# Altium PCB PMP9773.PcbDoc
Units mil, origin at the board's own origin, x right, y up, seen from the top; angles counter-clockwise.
Board outline 1500 x 600 mil, 2 copper layers (Top Layer, Bottom Layer), stack 62 mil thick; 36 components, 24 nets, 102 pads, 186 vias.
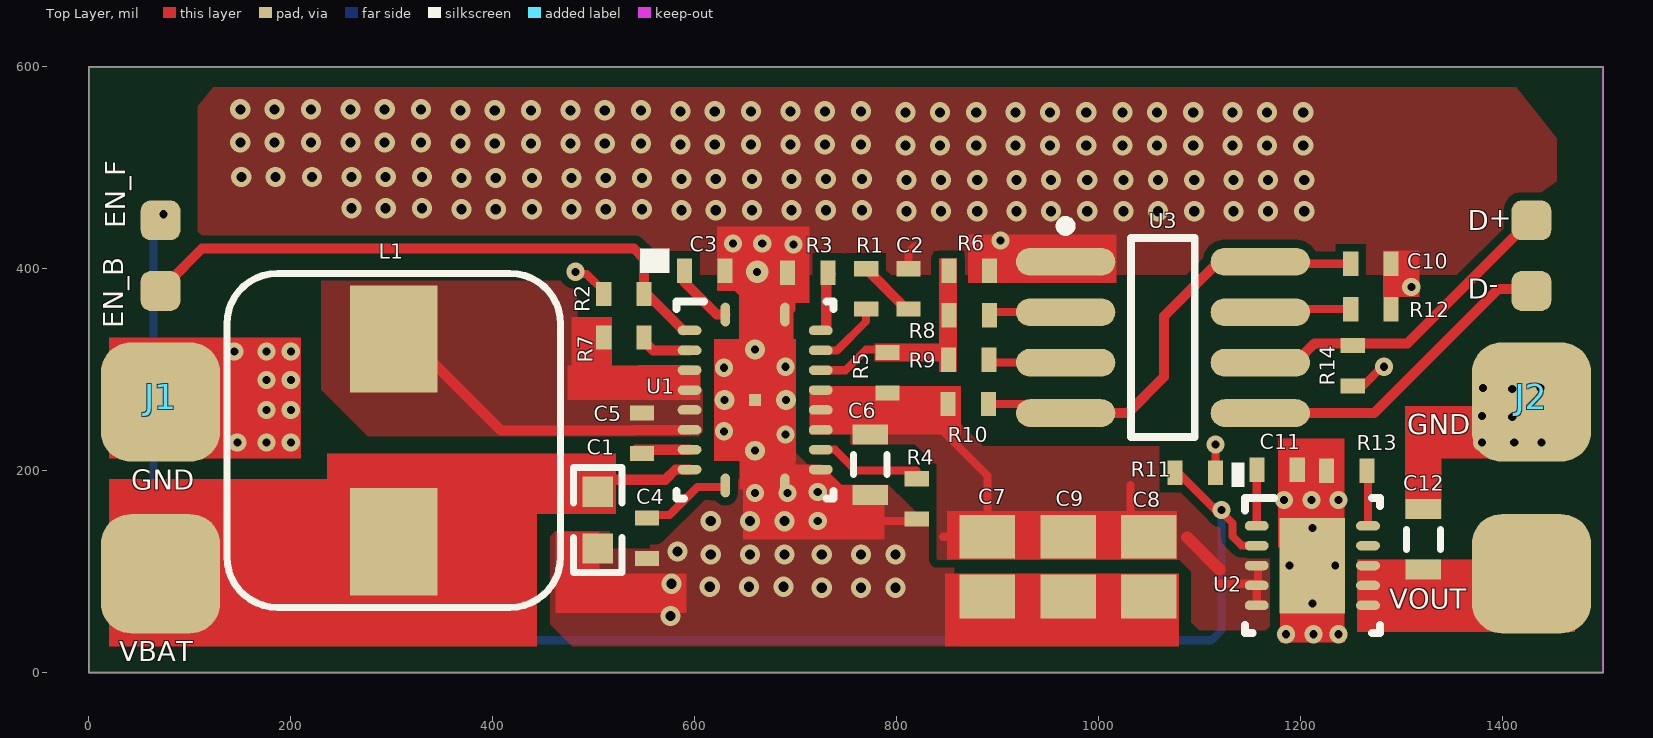
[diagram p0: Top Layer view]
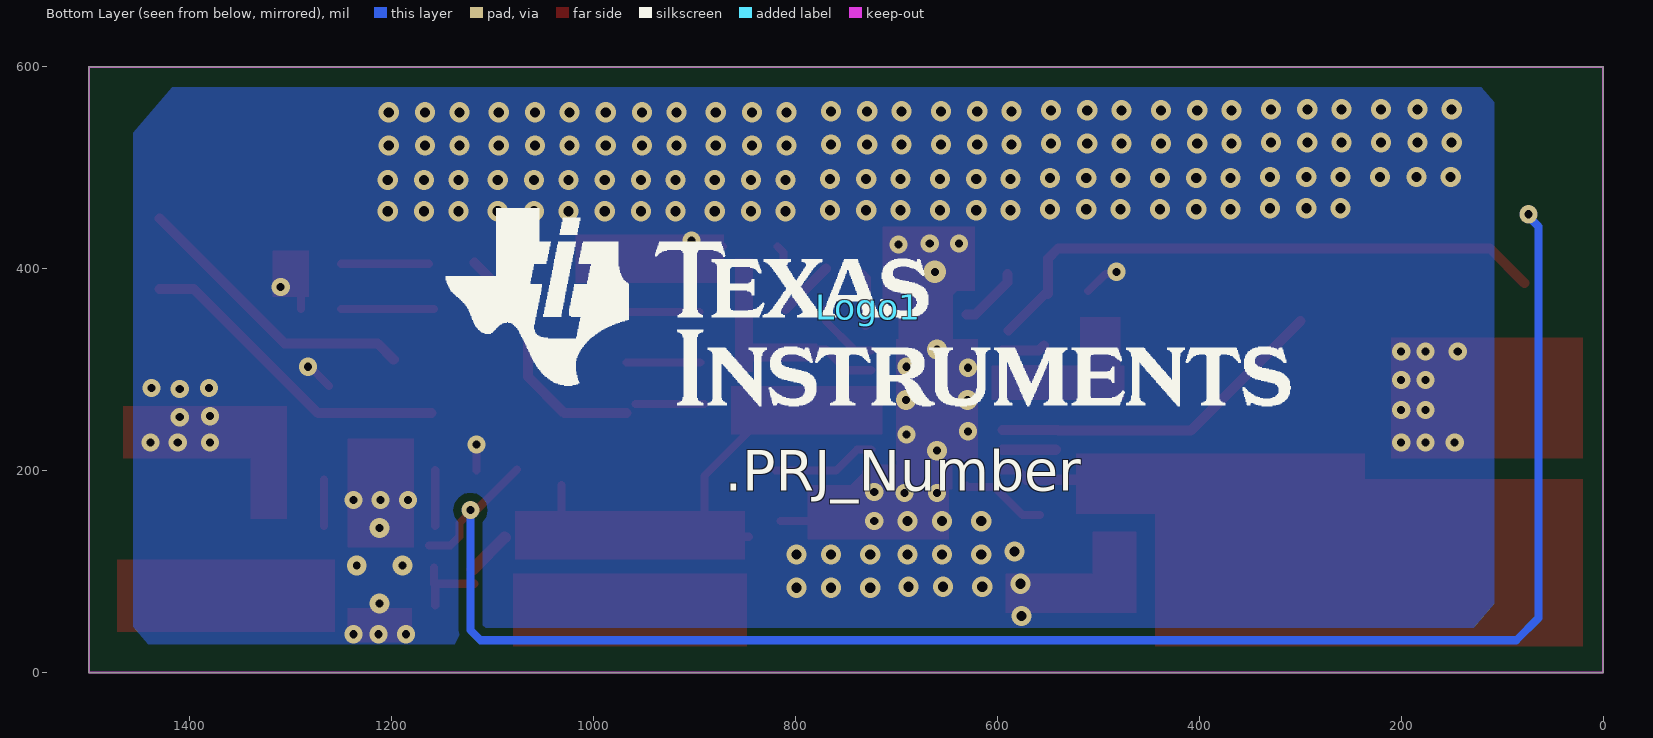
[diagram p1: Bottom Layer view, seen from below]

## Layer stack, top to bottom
Top Layer: signal copper 1.4
Dielectric: core 59.2, FR-4, Dk 4.8
Bottom Layer: signal copper 1.4

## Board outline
0,0 0,600 1500,600 1500,0

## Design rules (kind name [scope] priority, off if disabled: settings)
AcuteAngle [All] p1: minimum=4.50000000000000E+0001 checktracksonly=FALSE
AssemblyTestPointUsage [All] p1: valid=2
Clearance "Small Clearance" [InComponent('U1')] p1: gap=8
Clearance Clearance_BoardEdge_MountingHoles [OnCopper and InComponentClass('Mounting Holes') vs IsKeepOut] p2: gap=8
Clearance Clearance_BoardEdge_Poly [OnCopper and InPoly vs IsKeepOut] p3: gap=10
Clearance Clearance_BoardEdge [OnCopper and Not InComponentClass('Logo') and not InComponentClass('FiducialMark') and not InRegion(1000,500,4000,800) vs IsKeepOut] p4: gap=10
Clearance [All] p5: gap=8
ComponentClearance ComponentClearance_SHUNT [InComponentClass('Shunt')] p1: gap=0 collisioncheckmode=3 verticalgap=0 showdistances=FALSE
ComponentClearance ComponentClearance_Logo [All] p2: gap=10 collisioncheckmode=3 verticalgap=10 showdistances=FALSE
ComponentClearance ComponentClearance_ScrewToNut [(HasFootprint('NY PMS 440 0025 PH')) vs (HasFootprint('Keystone_1902C'))] p3: gap=5 collisioncheckmode=3 verticalgap=10 showdistances=FALSE
ComponentClearance ComponentClearance_MountingHoles [InComponentClass('Mounting Holes')] p4: gap=250 collisioncheckmode=3 verticalgap=100000 showdistances=FALSE
ComponentClearance ComponentClearance_SmallPassives [HasFootprint('0201*') or HasFootprint('0402*') or HasFootprint('0508') or HasFootprint('0603*') or HasFootprint('0612') or HasFootprint('0805*') or HasFootprint('0815*') or HasFootprint('0830*') or HasFootprint('1206*') or HasFootprint('1210*') or HasFootprint('1808*') or HasFootprint('1812*') or HasFootprint('1825*') or HasFootprint('2010*') or HasFootprint('2220*') or HasFootprint('2225*') or HasFootprint('2512*') or HasFootprint('2728*') or HasFootprint('3518*') vs HasFootprint('0201*') or HasFootprint('0402*') or HasFootprint('0508') or HasFootprint('0603*') or HasFootprint('0612') or HasFootprint('0805*') or HasFootprint('0815*') or HasFootprint('0830*') or HasFootprint('1206*') or HasFootprint('1210*') or HasFootprint('1808*') or HasFootprint('1812*') or HasFootprint('1825*') or HasFootprint('2010*') or HasFootprint('2220*') or HasFootprint('2225*') or HasFootprint('2512*') or HasFootprint('2728*') or HasFootprint('3518*')] p5: gap=20 collisioncheckmode=3 verticalgap=10 showdistances=FALSE
ComponentClearance ComponentClearance_THtoSMT [IsThruComponent vs IsSMTComponent] p6 off: gap=10 collisioncheckmode=3 verticalgap=100000 showdistances=FALSE
ComponentClearance ComponentClearance_THtoTH [IsThruComponent vs IsThruComponent] p7: gap=10.11 collisioncheckmode=3 verticalgap=100000 showdistances=FALSE
ComponentClearance [All] p8: gap=16 collisioncheckmode=3 verticalgap=10 showdistances=FALSE
DiffPairsRouting [All] p1: maxlimit=100 minlimit=10 mostfreqgap=10 maxuncoupledlength=1000
FabricationTestPointUsage TestPointUsage [All] p1: valid=2 allowmultiple=FALSE
FabricationTestpoint Testpoint [All] p1: side=3 testpointundercomponent=TRUE minsize=40 maxsize=100 preferedsize=60 minholesize=0 maxholesize=40 preferedholesize=32 testpointgrid=1 allowsidetop=TRUE allowsidebottom=TRUE usegrid=TRUE gridtolerance=0.01
FanoutControl Fanout_LCC [IsLCC] p1: bgadir=Out bgaviamode=Centered fanoutstyle=Auto fanoutdirection=Alternating viagrid=1 // Fanout_LCC (Default Rule)
FanoutControl Fanout_BGA [IsBGA] p2: bgadir=Out bgaviamode=Centered fanoutstyle=Auto fanoutdirection=Alternating viagrid=1 // Fanout_BGA (Default Rule)
FanoutControl Fanout_Default [All] p4: bgadir=Out bgaviamode=Centered fanoutstyle=Auto fanoutdirection=Alternating viagrid=1 // Fanout_Default (Default Rule)
FanoutControl Fanout_Small [(CompPinCount < 5)] p5: bgadir=Out bgaviamode=Centered fanoutstyle=Auto fanoutdirection=OutThenIn viagrid=1 // Fanout_Small (Default Rule)
HoleSize [All] p1: absolutevalues=TRUE maxlimit=80 minlimit=3.94 maxpercent=80.000 minpercent=20.000
HoleToHoleClearance [All] p1: gap=5 allowstackedmicrovias=TRUE
MinimumAnnularRing MinimumAnnularRing_small [TouchesRoom('BGA_Room')] p1: minimumring=2.8
MinimumAnnularRing [All] p2: minimumring=5
MinimumSolderMaskSliver MinimumSolderMaskSliver_Logo [InComponentClass('Logo') vs InComponentClass('Logo')] p1: minsoldermaskwidth=0.7
MinimumSolderMaskSliver [All] p2: minsoldermaskwidth=4
PlaneClearance [All] p1: clearance=10
PlaneConnect [All] p1: planeconnectstyle=Direct reliefexpansion=10 reliefentries=4 reliefconductorwidth=10 reliefairgap=10
PolygonConnect PolygonConnect-TH-Relief [IsPoly vs (IsThruPin)  And Not (InComponent('U3'))  And Not (InComponent('U4'))] p1: connectstyle=Direct reliefconductorwidth=20 reliefentries=4 polygonreliefangle="90 Angle" airgapwidth=10
PolygonConnect PolygonConnect-DirectConn [All] p2: connectstyle=Direct reliefconductorwidth=10 reliefentries=4 polygonreliefangle="90 Angle" airgapwidth=10
RoutingVias [All] p1: holewidth=10 width=22 viastyle="Through Hole" minholewidth=5.9 minwidth=11.8 maxholewidth=50 maxwidth=100
SMDToCorner [All] p1: distance=0
SilkToSilkClearance [All] p1: silktosilkclearance=3
SilkscreenOverComponentPads [All] p1: minsilkscreentomaskgap=2
SolderMaskExpansion [All] p1: expansion=1
Width [All] p1: maxlimit=100 minlimit=6 preferedwidth=10 checkconnectedcopper=TRUE
12 further rules are at their usual default settings.

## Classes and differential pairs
component class Logo: Logo1
component class PMP9773_Hardware: Logo1 ZZ1 ZZ2 ZZ3
component class AssemblyNote: ZZ1 ZZ2 ZZ3
component class PMP9773_Main: C1 C2 C3 C4 C5 C6 C7 C8 C9 C10 C11 C12 J1 J2 L1 R1 R2 R3 R4 R5 R6 R7 R8 R9 R10 R11 R12 R13 R14 U1 U2 U3

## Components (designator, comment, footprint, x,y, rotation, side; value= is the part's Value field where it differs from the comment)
C1 "GRM188R61A226ME15D" 0603_100_HV 504,151 r270 top
C2 "GRM155R71H103KA88D" 0402S 812,380 r90 top
C3 "GRM155R71C104KA88D" 0402S 610,398 r0 top
C4 "GRM155R61A473KA01D" 0402S 553,133 r270 top
C5 "GRM155R61C104KA88D" 0402S 548,237 r90 top
C6 "GRM188R61E105KA12D" 0603S 774,206 r270 top
C7 "GRM21BR61E226ME44" 0805L 890,105 r270 top
C8 "GRM21BR61E226ME44" 0805L 1050,105 r270 top
C9 "GRM21BR61E226ME44" 0805L 970,105 r270 top
C10 "GRM155R61A224KE19D" 0402S 1270,405 r0 top
C11 "GRM1535C1H101JDD5D" 0402S 1177,201 r0 top
C12 "GRM188R61E105KA12D" 0603S 1322,132 r90 top
J1 "Connector" Connector 71,198 r180 top
J2 "Connector" Connector 1429,198 r180 top
L1 "744311150" WE-HC4 302,230 r90 top
Logo1 "Texas Instruments" TI_Stacked_Overlay_Small 728,362 r180 bottom
R1 "CRCW04024K70JNED" 0402S 770,380 r270 top
R2 "CRCW04021M00FKED" 0402S 529.99,375 r0 top
R3 "CRCW0402100KFKED" 0402S 712,396 r0 top
R4 "RC0402JR-070RL" 0402s 820,172 r270 top
R5 "CRCW0402316KFKED" 0402S 791,297 r270 top
R6 "CRCW0402100KFKED" 0402S 872,398 r180 top
R7 "CRCW0402332KFKED" 0402S 530,332 r180 top
R8 "CRCW040295K3FKED" 0402S 872,354 r180 top
R9 "CRCW0402127KFKED" 0402S 871.5,309.87 r180 top
R10 "CRCW04023K01FKED" 0402S 871,266 r180 top
R11 "CRCW04021M00FKED" 0402S 1096,198 r180 top
R12 "CRCW0402127KFKED" 0402S 1270,360 r180 top
R13 "CRCW0402100KFKED" 0402S 1246,200 r0 top
R14 "CRCW0402390KJNED" 0402S 1252,304 r90 top
U1 "TPS61088RHLR" RHL0020A 660,270 r0 top
U2 "TPS2592AADRC" DRC0010J 1212,106 r0 top
U3 "CHY100" CHY100 1064,332 r0 top
ZZ1 "These assemblies are ESD sensitive, ESD precautions shall be observed." AssemblyNote 202,1133.11 r0 top
ZZ2 "These assemblies must be clean and free from flux and all contaminants. Use of no clean flux is not acceptable." AssemblyNote 202,1044.56 r0 top
ZZ3 "These assemblies must comply with workmanship standards IPC-A-610 Class 2, unless otherwise specified." AssemblyNote 202,956 r0 top

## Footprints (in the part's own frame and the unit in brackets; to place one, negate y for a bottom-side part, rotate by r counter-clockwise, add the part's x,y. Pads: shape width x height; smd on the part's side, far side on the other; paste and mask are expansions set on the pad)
0402S [mil] "Based on C0402S footprint from PADS legacy"
  rect 15x24 smd: 1(-20,0) 2(20,0)
  body extent -22,-12 22,12, height 24
0402s [mil] "Based on C0402S footprint from PADS legacy"
  rect 15x24 smd: 1(-20,0) 2(20,0)
  body extent -22,-12 22,12, height 24
0603_100_HV [mil] "SMD, 2-Leads, Body 1.6x0.8mm"
  rect 30x30 smd: 1(-28,0) 2(28,0)
  silkscreen extent -52,-24 52,24, body extent -34,-19 34,19, height 39
0603S [mil]
  rect 20x35 smd: 1(-30,0) 2(30,0)
  silkscreen extent -10,-17 10,17, body extent -34,-19 34,19, height 33
0805L [mm] "0805 from SM-752 data"
  rect 1.1x1.4 smd: 1(-0.75,0) 2(0.75,0)
  body extent -1.1,-0.72 1.1,0.72, height 1.1
AssemblyNote [mil] "Assembly Note"
CHY100 [mm]
  oval 2.5x0.7 smd: 1(-2.45,1.905) 2(-2.45,0.635) 3(-2.45,-0.635) 4(-2.45,-1.905) 5(2.45,-1.905) 6(2.45,-0.635) 7(2.45,0.635) 8(2.45,1.905)
  silkscreen extent -2.57,-2.5 0.8,2.93, body extent -2,-2.5 2,2.5, height 1.75
Connector [mm]
  rrect50% 3x3 smd: 1(0,2.54) 2(0,-1.778)
  rrect50% 1x1 smd: 3(0,-4.572) 4(0,-6.35)
DRC0010J [mm] "SON, 10-Leads, Body 3x3mm, Pitch 0.5mm, Thermal Pad 2.4x1.65mm, TI Recommended"
  oval 0.6x0.24 smd: 1(-1.4,1) 2(-1.4,0.5) 3(-1.4,0) 4(-1.4,-0.5) 5(-1.4,-1) 6(1.4,-1) 7(1.4,-0.5) 8(1.4,0) 9(1.4,0.5) 10(1.4,1)
  rect 1.65x2.4 smd paste-0.825: 11(0,0)
  Top Layer region: 0.135,1.1 0.365,1.1 0.365,1.5 0.135,1.5
  Top Layer region: -0.135,1.5 -0.365,1.5 -0.365,1.1 -0.135,1.1
  Top Layer region: -0.135,-1.1 -0.365,-1.1 -0.365,-1.5 -0.135,-1.5
  Top Layer region: 0.135,-1.5 0.365,-1.5 0.365,-1.1 0.135,-1.1
  silkscreen extent -1.7,-1.7 1.7,1.7, body extent -1.55,-1.55 1.55,1.55, height 1.01
RHL0020A [mm] "QFN, 20-Leads, Body 4.5x3.5mm, Pitch 0.5mm, Thermal Pad 3.05x2.05mm, TI Recommended"
  oval 0.24x0.6 smd: 1(-0.75,2.15) 10(-0.75,-2.15) 11(0.75,-2.15) 20(0.75,2.15)
  oval 0.6x0.24 smd: 2(-1.65,1.75) 3(-1.65,1.25) 4(-1.65,0.75) 5(-1.65,0.25) 6(-1.65,-0.25) 7(-1.65,-0.75) 8(-1.65,-1.25) 9(-1.65,-1.75) 12(1.65,-1.75) 13(1.65,-1.25) 14(1.65,-0.75) 15(1.65,-0.25) 16(1.65,0.25) 17(1.65,0.75) 18(1.65,1.25) 19(1.65,1.75)
  rect 0.3x0.3 smd paste-0.15 mask+0: 21(0,0)
  Top Layer region: 0.16,2.25 0.16,1.925 -0.16,1.925 -0.16,2.25 -0.39,2.25 -0.39,1.525 -1.025,1.525 -1.025,-1.525 -0.39,-1.525 -0.39,-2.25 -0.16,-2.25 -0.16,-1.925 0.16,-1.925 0.16,-2.25 0.39,-2.25 0.39,-1.525 1.025,-1.525 1.025,1.525 0.39,1.525 0.39,2.25
  silkscreen extent -1.98,-2.47 1.98,2.47, body extent -1.82,-2.33 1.83,2.32, height 1.01
TI_Stacked_Overlay_Small [mil]
  silkscreen extent -418,-98 418,98
WE-HC4 [mm] "Wurth Electronik recommended land pattern"
  rect 2.7x2.2 smd: 1(-2.55,0) 2(2.55,0)
  silkscreen extent -4.2,-4.2 4.2,4.2, body extent -3.66,-3.61 3.66,3.61, height 4

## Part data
C1: "CAP, CERM, 22 µF, 10 V, +/- 20%, X5R, 0603"
C2: "CAP, CERM, 0.01 µF, 50 V, +/- 10%, X7R, 0402"
C3: "CAP, CERM, 0.1 µF, 16 V, +/- 10%, X7R, 0402"
C4: "CAP, CERM, 0.047uF, 10V, +/-10%, X5R, 0402"
C5: "CAP, CERM, 0.1uF, 16V, +/-10%, X5R, 0402"
C6 C12: "CAP, CERM, 1 µF, 25 V, +/- 10%, X5R, 0603"
C7 C8 C9: "CAP, CERM, 22 µF, 25 V, +/- 20%, X5R, 0805"
C10: "CAP, CERM, 0.22 µF, 10 V, +/- 10%, X5R, 0402"
C11: "CAP, CERM, 100 pF, 50 V, +/- 5%, C0G/NP0, 0402"
L1: "Inductor, Shielded Drum Core, Superflux, 1.5 µH, 11 A, 0.0078 ohm, SMD"
Logo1: library part TI_Logo, "Texas Instrument Corporate Signature"
R1: "RES, 4.7 k, 5%, 0.063 W, 0402"
R2 R11: "RES, 1.00 M, 1%, 0.063 W, 0402"
R3 R13: "RES, 100k ohm, 1%, 0.063W, 0402"
R4: "RES, 0 ohm, 5%, 0.063W, 0402"
R5: "RES, 316 k, 1%, 0.063 W, 0402"
R6: "RES, 100 k, 1%, 0.063 W, 0402"
R7: "RES, 332 k, 1%, 0.063 W, 0402"
R8: "RES, 95.3 k, 1%, 0.063 W, 0402"
R9 R12: "RES, 127 k, 1%, 0.063 W, 0402"
R10: "RES, 3.01 k, 1%, 0.063 W, 0402"
R14: "RES, 390 k, 5%, 0.063 W, 0402"
U1: "13.2-V Output, Synchronous Boost Converter with 10-A Switch, RHL0020A"
U2: "12V eFuse with Integrated Blocking FET Driver, Auto Retry, DRC0010J"
ZZ1 ZZ2 ZZ3: library part AssemblyNote

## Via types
v1: diameter 20, hole 10, Top Layer to Bottom Layer, 135 vias
v2: diameter 18, hole 8, Top Layer to Bottom Layer, 42 vias
v3: diameter 19.68, hole 7.87, Top Layer to Bottom Layer, 8 vias
v4: diameter 22, hole 8, Top Layer to Bottom Layer, 1 vias

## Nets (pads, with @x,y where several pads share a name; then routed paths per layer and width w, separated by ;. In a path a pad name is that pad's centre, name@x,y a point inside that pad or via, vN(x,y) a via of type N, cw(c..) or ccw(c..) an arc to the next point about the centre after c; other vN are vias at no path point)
D+: J2.4 R14.2 U3.6 | length 291.9
  Top Layer w10: U3.6@1198,310 1214,326 1298,326 ; 1296.11,326 1306,326 J2.4@1430,450
D-: J2.3 U3.5 | length 320.5
  Top Layer w10: U3.5 1273,257 1396,380 J2.3@1430,380
EN_B: J1.3 R2.2 U1.2 | length 579.2
  Top Layer w10: J1.3@78,386 112,420 540,420 549.99,410.01 R2.2 552.88,375 U1.2@588.99,338.89
EN_F: J1.4 R11.2 U2.2 | length 1719.5
  Top Layer w8: R11.2@1076,201 1116,161 1120,161 1133.07,147.93 1133.07,134.93 1142,126 U2.2@1163,126
  Bottom Layer w8: v2@75,453 64,442 64,54 86,32 1112,32 1122,42 v2(1122,161)
  other v2: 74,454
GND: C1.2 C2.2 C3.2 C4.2 C6.2 C7.2 C8.2 C9.2 C10.2 C11.2 C12.2 J1.2 J2.2 R2.1 R3.1 R4.2 R6.1 R11.1 R12.1 R13.1 R14.1 U1.11 U1.12 U1.20 U1.21 U2.11 U3.1 | length 784.1
  Top Layer w8: v2@482,395 493,395 R2.1@510,378 ; 670,202 689.53,202 ; 675,197 675,150 R4.2@815,150 ; U1.11 689.53,202 ; 689.53,226.47 689.53,202 ; C6.2@770,175 751.06,175 U1.12 724.06,202 689.53,202 ; C2.2 812,416 818,422 ; 872,422 R6.1@890,404 ; R6.1 U3.1@958.54,398 ; R11.1@1116,200 1116,201 v2(1116,226) ; U2.11@1197,135 C11.2 ; R14.1@1262,284 1283,305 v2@1286,305 ; R12.1 C10.2
  Top Layer w10: C3.2@630,395 660,365 660,345.78 ; 670.24,354.65 U1.20 695,360.11 R3.1@695,395
  other v1: 576,56 726,84 765,84 799,84 615,85 654,85 688,85 577,88 616,117 655,117 689,117 726,117 765,117 799,117 583,120 616,150 655,150 689,150 810,457 844,457 880,457 919,457 953,457 989,457 1025,457 1059,457 1095,457 1134,457 1168,457 1204,457 587,458 621,458 657,458 696,458 730,458 766,458 369,459 403,459 439,459 478,459 512,459 548,459 260,460 294,460 330,460 810,488 844,488 880,488 919,488 953,488 989,488 1025,488 1059,488 1095,488 1134,488 1168,488 1204,488 587,489 621,489 657,489 696,489 730,489 766,489 369,490 403,490 439,490 478,490 512,490 548,490 151,491 185,491 221,491 260,491 294,491 330,491 809,522 843,522 879,522 918,522 952,522 988,522 1024,522 1058,522 1094,522 1133,522 1167,522 1203,522 586,523 620,523 656,523 695,523 729,523 765,523 368,524 402,524 438,524 477,524 511,524 547,524 150,525 184,525 220,525 259,525 293,525 329,525 809,555 843,555 879,555 918,555 952,555 988,555 1024,555 1058,555 1094,555 1133,555 1167,555 1203,555 586,556 620,556 656,556 695,556 729,556 765,556 368,557 402,557 438,557 477,557 511,557 547,557 150,558 184,558 220,558 259,558 293,558 329,558
  other v2: 1186,38 1213,38 1238,38 722,150 1184,171 1211,171 1238,171 660,178 692,178 722,179 147,228 176,228 200,228 1380,228 1412,228 1439,228 690,236 629,239 1410,253 1380,254 176,260 200,260 1410,281 1381,282 1438,282 176,290 200,290 629,302 690,303 1283,303 144,318 176,318 200,318 1310,382 482,397 698,424 638,425 667,425 903,428
  other v3: 1212,68.6 1189.36,106 1234.64,106 1212,143.4 660,219.8 629.49,270 690.51,270 660,320.2
  other v4: 662,397
NetC2_1: C2.1 R1.1 | length 56.6
  Top Layer w10: R1.1 C2.1@810,360
NetC3_1: C3.1 U1.1 | length 62.1
  Top Layer w10: C3.1@590,395 590,386.65 622.01,354.65 U1.1
NetC4_1: C4.1 U1.10 | length 84.6
  Top Layer w8: C4.1@558,156 575,156 603,184 629.12,184 U1.10
NetC5_1: C5.1 U1.8 | length 53.3
  Top Layer w10: C5.1@541.78,220.78 U1.8
NetC5_2: C5.2 L1.2 R7.2 U1.4 U1.5 U1.6 U1.7 | length 388.9
  Top Layer w10: L1.2@300,348.11 408.11,240 540,240 ; 540.47,240.47 U1.7 ; 545.48,299.52 U1.4
NetC6_1: C6.1 C7.1 C8.1 C9.1 R5.2 R10.2 U1.14 U1.15 U1.16 U2.3 U2.4 U2.5 | length 774.8
  Top Layer w8: C6.1@764.53,240.47 U1.14 U1.15 U1.16 805.16,279.84 890,195 C7.1 ; 846.02,134.53 C7.1 ; 850,237 R10.2@850,266 ; C8.1@1032,128 C8.1@1032,134.53 ; 1032,186 C8.1@1032,134.53 ; C8.1@1062,126 1062,134.53 C8.1 C8.1@1032,134.53 ; 1118,88 U2.4@1156.88,88 ; U2.5 U2.4 U2.4@1156.88,88 ; U2.4@1156.88,89.12 U2.4@1156.88,88 ; U2.3@1158,104 1158,88 U2.4@1156.88,88 ; C7.1 C9.1 C8.1@1032,134.53
  Top Layer w12: 1088,134 1120,102
NetC10_1: C10.1 R10.1 U3.4 U3.8 | length 402.9
  Top Layer w8: R10.1@890,266 U3.4@958.54,266 ; U3.8@1163,405 C10.1
  Top Layer w10: U3.4 1029,257 1065,293 1065,353 U3.8@1118,406
NetC11_1: C11.1 U2.1 | length 55.5
  Top Layer w8: U2.1 C11.1@1156.88,200.88
NetR1_2: R1.2 U1.18 | length 69
  Top Layer w8: U1.18 741.21,319.21 770,348 R1.2
NetR3_2: R3.2 U1.19 | length 52.5
  Top Layer w10: 730.48,344.41 730.48,390.48 R3.2@735,395
NetR4_1: R4.1 U1.13 | length 103.6
  Top Layer w8: U1.13 739.22,220.78 760,200 820,200
NetR5_1: R5.1 R6.2 R8.2 R9.2 U1.17 | length 223.2
  Top Layer w8: U1.17 749.52,299.52 770,320 788,320 R9.2@851.5,320 ; R9.2 R9.2@851.5,320 ; R6.2@851.5,397.5 R9.2@851.5,320 ; R9.2@852,320 R9.2@851.5,320
NetR7_1: R7.1 U1.3 | length 43
  Top Layer w10: R7.1@554,324 558.79,319.21 U1.3
NetR12_2: R12.2 U3.7 | length 92
  Top Layer w8: U3.7@1158,360 R12.2
NetR13_2: R13.2 U2.10 | length 45.7
  Top Layer w8: U2.10 R13.2@1267.12,191.12
V1: R8.1 U3.2 | length 72.5
  Top Layer w8: R8.1@895,357 U3.2
V2: R9.1 U3.3 | length 73.2
  Top Layer w8: R9.1@894.38,307 U3.3
VIN: C1.1 J1.1 L1.1 U1.9 | length 503.6
  Top Layer w10: J1.1@70,100 288.11,100 300,111.89 389.89,111.89 444,166 ; C1.1@497,191 571,191 581.1,201.1 U1.9
VOUT: C12.1 J2.1 U2.6 U2.7 U2.8 | length 38.3
  Top Layer w8: U2.6 U2.7 U2.8@1267.12,104.88
pads on no net: U2.9

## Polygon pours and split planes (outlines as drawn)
GND on Top Layer "Top Layer-No Net 4" (solid, pour order 11): 645,192.08 581,192.08 556,167.08 529,140.08 506,140.08 462,140.08 461,139.08 457,135.08 457,92.08 457,48.08 465,40.08 479,26.08 857,26.08 857,121.08 792,186.08 732,186.08 688,230.08 650,192.08 645,192.08
GND on Top Layer "Top Layer-No Net 3" (solid, pour order 9): 108,394 108,561.02 123,580 1414,580 1454,529.39 1454,401.59 1448,394 108,394
NetC6_1 on Top Layer "Top Layer-No Net 2" (solid, pour order 5): 1038,224 1078,224 1078,190 1082,186 1142,126 1170,126 1170,93 1107,93 1083,117 1038,162 1038,224
NetC5_2 on Top Layer "Top Layer-No Net 1" (solid, pour order 4): 230,388 472,388 482,378 484,376 484,286 602,286 608,280 608,238 604,234 276,234 230,280 230,388
NetC6_1 on Top Layer "Top Layer-No Net" (solid, pour order 2): 754,226 818,226 840,204 840,112 1080,112 1092,100 1092,50 1100,42 1166,42 1170,46 1170,108 1166,112 1156,112 1102,112 1094,120 1094,144 1078,160 1058,160 1046,172 1046,216 1038,224 886,224 860,250 856,254 754,254 754,226
GND on Bottom Layer "Bottom Layer-No Net" (solid, pour order 6): 120.78,580 1417.67,580 1456,534.63 1456,45.64 1441.09,28 142.07,28 108,68.33 108,564.88 120.78,580

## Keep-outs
Keep-Out Layer:
  the board outline again, w2
  text ".Layer_Name" at 517,-918.49 h60

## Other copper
Top Layer:
  rectangle net VIN: 236,157 522,217
  rectangle net NetR5_1: 778,308 850,326
  rectangle net NetR5_1: 842,298 860,410
  rectangle net GND: 716,132 788,186
  rectangle net GND: 682,132 734,200
  rectangle net GND: 648,132 700,220
  rectangle net GND: 684,366 714,442
  rectangle net GND: 622,378 656,442
  rectangle net GND: 644,304 698,442
  rectangle net GND: 1180,30 1244,64
  rectangle net GND: 1178,124 1244,232
  rectangle net GND: 1304,152 1340,264
  rectangle net GND: 871,386 1018,434
  rectangle net GND: 1282,372 1318,418
  rectangle net NetC5_2: 478,294 518,352
  rectangle net NetC5_2: 474,270 606,304
  rectangle net GND: 1306,212 1466,264
  rectangle net VOUT: 1256,40 1472,112
  rectangle net GND: 20,212 210,332
  rectangle net GND: 462,59 592,98
  rectangle net GND: 462,74 506,140
  rectangle net VIN: 20,26 444,192
  rectangle net NetC6_1: 714,236 864,284
  rectangle net NetC6_1: 850,112 1078,160
  rectangle net GND: 848,26 1080,98
  text ".Layer_Name" at 517,-918.49 h60
Bottom Layer:
  text ".Layer_Name" at 517,-918.49 h60

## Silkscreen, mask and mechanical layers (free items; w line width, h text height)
Top Overlay:
  rectangle: 546,396 575,420
  rectangle: 1132,184 1145,208
  text "D+" at 1366,458 h20 r180
  text "EN_F" at 36,440 h20 r90
  text "D-" at 1366,390 h20 r180
  text "EN_B" at 34,341 h20 r90
  text "GND" at 1306,236 h20
  text "GND" at 42,181 h20
  text "VOUT" at 1288,63 h20
  text "VBAT" at 30,11 h20
  text ".Layer_Name" at 517,-918.49 h60
Bottom Overlay:
  text ".PRJ_Number" at 870,180 h40
  text ".Layer_Name" at 517,-918.49 h60
Top Paste:
  text ".Layer_Name" at 517,-918.49 h60
Bottom Paste:
  text ".Layer_Name" at 517,-918.49 h60
Top Solder:
  text ".Layer_Name" at 517,-918.49 h60
  text ".Layer_Name" at 517,-918.49 h60
Bottom Solder:
  text ".Layer_Name" at 517,-918.49 h60
Drill Guide:
  text ".Layer_Name" at 517,-918.49 h60
M1 Board Outline:
  lines w2: 0,0 0,600 40,600 1500,600 1500,0 0,0
  text ".Layer_Name" at 517,-918.49 h60
M2 Board Dimensions:
  rectangle: -60,-345.5 65,-220.5
  rectangle: 65,-470.5 440,-345.5
  lines w7: -60,-345.5 940,-345.5 ; 65,-470.5 65,-220.5 ; 190,-470.5 190,-220.5 ; 440,-470.5 440,-220.5 ; 690,-470.5 690,-220.5 ; -60,-470.5 940,-470.5 940,-220.5 -60,-220.5 -60,-470.5
  text ".Layer_Name" at 517,-918.49 h60
M3 3D STEP Top:
  text ".Layer_Name" at 517,-918.49 h60
M4 3D STEP Bottom:
  text ".Layer_Name" at 517,-918.49 h60
M5 Assembly Top:
  lines w10: -352,-990.17 6248,-990.17 ; -352,-786.83 6250,-786.83 ; -352,-583.5 -352,-1193.5 3653,-1193.5 6250,-1193.5 6250,-583.5 -351.5,-583.5 -351.5,-1193.5 1224,-1193.5 ; 2113,-1193.5 2113,-583.5 ; 3380,-786.83 3380,-583.5 ; 4220,-786.83 4220,-583.5 ; 4842,-1200 4842,-997.17
  text "COMPONENTS MARKED 'DNP' SHOULD NOT BE POPULATED." at 1093.5,-378.5 h60
  text "ASSEMBLY VARIANT:" at 1093,-494 h60
  text ".VariantName" at 2129,-494 h60
  text "PCB VIEWED FROM TOP SIDE" at -288.5,-715.67 h60
  text "BOARD #:" at 2188,-715.67 h60
  text ".PRJ_Number" at 2733.5,-715.67 h60
  text "REV:" at 3578,-715.67 h60
  text ".PCB_Rev" at 3869.5,-715.67 h60
  text "SVN REV:" at 4416,-715.67 h60
  text ".VersionControl_RevNumber" at 4922,-715.67 h60
  text "IGNORE ->" at -288.5,-918.49 h60
  text "PLOT NAME =" at -288.5,-1124.34 h60
  text ".plot_File_Name" at 517,-1124.34 h60
  text "GENERATED    :" at 2190,-1124.34 h60
  text ".Print_Date" at 3059.5,-1124.34 h60
  text ".Print_Time" at 3788.5,-1124.34 h60
  text "TEXAS INSTRUMENTS" at 5053,-1124.34 h60
M6 Assembly Bottom:
  lines w10: -352.5,-787.33 6249.5,-787.33 ; -350.5,-990.67 6249.5,-990.67 ; 1055.5,-1200.5 1055.5,-997.67 ; 1677.5,-787.33 1677.5,-584 ; 2517.5,-787.33 2517.5,-584 ; 3784.5,-1194 3784.5,-584 ; 4673.5,-1194 6249,-1194 6249,-584 -352.5,-584 -352.5,-1194 2244.5,-1194 6249.5,-1194 6249.5,-584
  text "COMPONENTS MARKED 'DNP' SHOULD NOT BE POPULATED." at 6042,-378 h60
  text ".VariantName" at 4998,-494 h60
  text "ASSEMBLY VARIANT:" at 6037,-494 h60
  text ".VersionControl_RevNumber" at 975.5,-716.17 h60
  text "SVN REV:" at 1481.5,-716.17 h60
  text ".PCB_Rev" at 2028,-716.17 h60
  text "REV:" at 2319.5,-716.17 h60
  text ".PRJ_Number" at 3164,-716.17 h60
  text "BOARD #:" at 3709.5,-716.17 h60
  text "PCB VIEWED FROM BOTTOM SIDE" at 6186,-716.17 h60
  text "IGNORE ->" at 2487.85,-918.49 h60
  text "TEXAS INSTRUMENTS" at 844.5,-1124.84 h60
  text ".Print_Time" at 2109,-1124.84 h60
  text ".Print_Date" at 2838,-1124.84 h60
  text "GENERATED    :" at 3707.5,-1124.84 h60
  text ".plot_File_Name" at 5380.5,-1124.84 h60
  text "PLOT NAME =" at 6186,-1124.84 h60
M9 Title Sheet:
  drawing of 57 lines, arcs and shapes, not listed
  text "1" at 679.84,7976.5 h70
  text "2" at 3175.5,7976.5 h70
  text "3" at 5664.84,7976.5 h70
  text "4" at 8171.51,7976.5 h70
  text "5" at 10670.5,7976.5 h70
  text "6" at 13175.5,7976.5 h70
  text "A" at -476.5,6833.5 h70
  text "A" at 14323.5,6833.5 h70
  text "B" at -476.5,4453.5 h70
  text "B" at 14323.5,4453.5 h70
  text "C" at -476.5,2078.5 h70
  text "C" at 14323.5,2078.5 h70
  text "PROJECT TITLE:" at 11283.5,217.5 h45
  text ".PRJ_Title" at 11333.5,84.17 h70
  text "DESIGNED FOR:" at 11283.5,-83.5 h45
  text ".PRJ_Customer" at 11333.5,-223.5 h70
  text "D" at -476.5,-291.5 h70
  text "D" at 14323.5,-291.5 h70
  text "FILE NAME:" at 11283.5,-383.5 h45
  text ".PCB_File_Name_No_Path" at 11333.5,-503.5 h70
  text "Texas Instruments (TI) and/or its licensors do not warrant the accuracy or completeness of this specification" at 6314,-665.34 h45
  text "ENGINEER:" at 11283.5,-673.5 h45
  text "LAYOUT BY:" at 12788.5,-673.5 h45
  text "or any information contained therein. TI and/or its licensors do not warrant that this design will meet" at 6269.01,-778 h45
  text ".PRJ_Engineer" at 11333.5,-828.49 h70
  text ".PCB_Layout" at 12839,-828.49 h70
  text "the specifications, will be suitable for your application or fit for any particular purpose, or will operate in" at 6269.01,-890.67 h45
  text ".Layer_Name" at 517,-918.49 h60
  text "ALTIUM DESIGNER VERSION:" at 12788.5,-983.5 h45
  text "an implementation. TI and/or its licensors do not warrant that the design is production worthy. You should" at 6269.01,-1003.33 h45
  text "completely validate and test your design implementation to confirm the system functionality for your application." at 6314,-1116 h45
  text ".print_Scale" at 11333.5,-1116.83 h70
  text ".Application_BuildNumber" at 12839,-1116.83 h70
  text "1" at 679.84,-1323.5 h70
  text "2" at 3175.5,-1323.5 h70
  text "3" at 5664.84,-1323.5 h70
  text "4" at 8171.51,-1323.5 h70
  text "5" at 10670.5,-1323.5 h70
  text "6" at 13175.5,-1323.5 h70
M10 Fab Notes:
  drawing of 185 lines, arcs and shapes, not listed
  text "DESIGN INFORMATION" at 12321.02,5850 h60
  text "MIN. TRACK WIDTH:" at 11676.46,5670 h60
  text "8" at 12772.7,5670 h60
  text "MIL" at 12927.46,5670 h60
  text "MIN. CLEARANCE:" at 11676.46,5538 h60
  text "8" at 12712.7,5538 h60
  text "MIL" at 12927.46,5538 h60
  text "MIN. VIA PAD SIZE:" at 11676.46,5406 h60
  text "20" at 12742.71,5406 h60
  text "MIL" at 12927.46,5406 h60
  text "0.05mm (2MIL)" at 12371.46,5264.29 h60
  text "MINIMUM ANNULAR RING" at 11347.23,5260 h60
  text "EXTERNAL" at 13079.46,5260 h60
  text "PER" at 11547.23,5142 h60
  text "IPC-D-275 CLASS 2 LEVEL C" at 11767.23,5142 h60
  text "MIL, HOLES" at 13255.46,5029.71 h60
  text "+/-" at 12863,5029 h60
  text "+/-" at 13717,5029 h60
  text "REGISTRATION TOLERANCES:" at 11347.23,5024 h60
  text "METAL" at 12547,5024 h60
  text "5" at 13123.2,5024 h60
  text "3" at 13956.2,5024 h60
  text "MIL" at 14072.46,5024 h60
  text "MATERIAL:" at 11272.46,4814.54 h60
  text "FR-4 High Tg" at 12258.9,4674.21 h60
  text "FR-408" at 11693.46,4665.64 h60
  text "OTHER" at 13181.46,4665.64 h60
  text "X" at 11543.46,4659.64 h60
  text "62 MIL (1.6mm) +/-10%" at 12013.56,4502.92 h60
  text "THICKNESS:" at 11347.23,4498.64 h60
  text "X" at 11885.4,4498.64 h60
  text "OTHER" at 13298.46,4498.64 h60
  text "TOLERANCE:" at 11347.23,4340.64 h60
  text "X" at 12186.53,4340.64 h60
  text "ANSI IPC-6012 TYPE 3 CLASS 2" at 12373.48,4340.64 h60
  text "OTHER +/-" at 12373.46,4184.64 h60
  text "BOW & TWIST:" at 11347.23,4027.64 h60
  text "X" at 12186.53,4027.64 h60
  text "ANSI IPC-6012 TYPE 3 CLASS 2" at 12373.48,4027.64 h60
  text "OTHER +/-" at 12373.46,3869.13 h60
  text "DRILLING:" at 11272.46,3730.64 h60
  text "REFERENCE:" at 11347.23,3613.64 h60
  text "X" at 11995.46,3613.64 h60
  text "AS SHOWN" at 12182.46,3613.64 h60
  text "X" at 12896.46,3613.64 h60
  text "NC_DRILL FILES" at 13033.46,3613.64 h60
  text "PTH MIN COPPER THICKNESS:" at 11347.23,3455.64 h60
  text "X" at 12697.46,3455.64 h60
  text "1MIL" at 12834.46,3455.64 h60
  text "OTHER" at 13331.46,3455.64 h60
  text "BOARD FINISH:" at 11272.46,3296.64 h60
  text "SILKSCREEN:" at 11427.68,3178.64 h60
  text "X" at 12376.46,3178.64 h60
  text "TOP" at 12502.46,3178.64 h60
  text "X" at 12886.46,3178.64 h60
  text "BOTTOM" at 13013.46,3178.64 h60
  text "SILKSCREEN COLOR:" at 11427.68,3011.64 h60
  text "X" at 12375.42,3011.64 h60
  text "WHITE" at 12502.46,3011.64 h60
  text "OTHER" at 13013.46,3011.64 h60
  text "SOLDER RESIST COLOR:" at 11427.68,2841.64 h60
  text "X" at 11995.42,2682.44 h60
  text "GREEN" at 12122.46,2682.44 h60
  text "BLUE" at 12713.46,2682.44 h60
  text "OTHER" at 13251.46,2682.44 h60
  text "IMMERSION GOLD (ENIG)" at 12333.46,2493.92 h60
  text "ENEPIG" at 13671,2490.64 h60
  text "SURFACE FINISH:" at 11272.46,2489.64 h60
  text "IMM. TIN/SILVER OR EQUIV" at 11602,2332.64 h60
  text "OTHER" at 13033.46,2332.64 h60
  text "X" at 11433.46,2330.64 h60
  text "ARRAY/PANEL:" at 11272.46,2153.64 h60
  text "CUT AND TRIM PER MECH LAYER 1" at 12333.46,2149.35 h60
  text "N.C. ROUTE" at 12333.46,1997.64 h60
  text "X" at 13012.46,1997.64 h60
  text "V. SCORE" at 13199.46,1997.64 h60
  text "CERTIFICATION:" at 11272.46,1860.64 h60
  text "MATERIALS AND WORKMANSHIP FOR ALL PCBS" at 11997.46,1860.64 h60
  text "TO MEET OR EXCEED THE REQUIREMENTS OF:" at 11997.46,1762.64 h60
  text "X" at 11623.96,1626.13 h60
  text "ANSI IPC-A-600F CLASS ->" at 11762.96,1626.13 h60
  text "X" at 13402.02,1626.13 h60
  text "2" at 13520.96,1626.14 h60
  text "1" at 13205.96,1624.64 h60
  text "3" at 13874.96,1624.64 h60
  text "X" at 11626.02,1466.64 h60
  text "UL 94V-0" at 11762.96,1466.64 h60
  text "X" at 12438.02,1466.64 h60
  text "RoHS" at 12574.96,1466.64 h60
  text "OTHER" at 13219.36,1466.64 h60
  text "PER ORDER" at 13616.42,1466.64 h60
  text "ADDITIONAL REQUIREMENTS:" at 11272.46,1325.64 h60
  text "MICROSECTION:" at 11347.23,1210.64 h60
  text "YES" at 12252.96,1210.64 h60
  text "REQUIRED" at 13114.46,1054.49 h60
  text "BARE BOARD ELEC. TEST:" at 11347.23,1051.64 h60
  text "NONE" at 12652.96,1051.64 h60
  text "X" at 12987.46,1051.64 h60
  text "PER ORDER" at 13706.46,1051.64 h60
  text "MANUFACTURER'S UL:" at 11347.23,894.64 h60
  text "RAIL" at 12512.96,890.35 h60
  text "METAL" at 13004.77,890.35 h60
  text "X" at 13380,890 h60
  text "SILK" at 13516.46,890.35 h60
  text ".Layer_Name" at 517,-918.49 h60
M11 Gerber Information:
  lines w10: -352,-990.17 6248,-990.17 ; -352,-786.83 6250,-786.83 ; -352,-583.5 -352,-1193.5 3653,-1193.5 6250,-1193.5 6250,-583.5 -351.5,-583.5 -351.5,-1193.5 1224,-1193.5 ; 2113,-1193.5 2113,-583.5 ; 3380,-786.83 3380,-583.5 ; 4220,-786.83 4220,-583.5 ; 4842,-1200 4842,-997.17
  text "ALL ARTWORK VIEWED FROM TOP SIDE" at -288.5,-715.67 h60
  text "BOARD #:" at 2188,-715.67 h60
  text ".PRJ_Number" at 2733.5,-715.67 h60
  text "REV:" at 3578,-715.67 h60
  text ".PCB_Rev" at 3869.5,-715.67 h60
  text "SVN REV:" at 4416,-715.67 h60
  text ".VersionControl_RevNumber" at 4922,-715.67 h60
  text "LAYER NAME =" at -288.5,-918.49 h60
  text "PLOT NAME =" at -288.5,-1124.34 h60
  text ".plot_File_Name" at 517,-1124.34 h60
  text "GENERATED    :" at 2190,-1124.34 h60
  text ".Print_Date" at 3059.5,-1124.34 h60
  text ".Print_Time" at 3788.5,-1124.34 h60
  text "TEXAS INSTRUMENTS" at 5053,-1124.34 h60
M12 Stackup:
  lines w6: 11300,7400 13850,7400 ; 11300,7504.4 13850,7504.4 ; 11240,6915 ccw(c11274,6915) 11274,6881 13876,6881 ccw(c13876,6915) 13910,6915 13910,7621 ccw(c13876,7621) 13876,7655 11274,7655 ccw(c11274,7621) 11240,7621 11240,6915
  text "The Stackup Legend below this is static." at 11545.5,7814.5 h60
  text "If you change the stackup, update the Legend." at 11555.5,7724.5 h60
  text "Layer Stack Up Detail for: PMP9773" at 11300,7537.1 h57
  text "Layer" at 11300,7465.4 h24
  text "Gerber" at 12195.81,7465.4 h24
  text "Copper" at 12759.33,7465.4 h24
  text "Dielectric" at 13362.04,7465.4 h24
  text "Name" at 11300,7417.4 h24
  text "Document" at 12195.81,7417.4 h24
  text "Thickness" at 12759.33,7417.4 h24
  text "Material" at 13362.04,7417.4 h24
  text "Top Solder Mask" at 11300,7324.44 h34
  text "(.GTS)" at 12195.81,7324.44 h34
  text "Solder Resist" at 13362.04,7324.44 h34
  text "Top Layer" at 11300,7227.69 h34
  text "(.GTL)" at 12195.81,7227.69 h34
  text "2.8mil" at 12759.33,7227.69 h34
  text "FR-4" at 13362.04,7179.31 h34
  text "Bottom Layer" at 11300,7130.94 h34
  text "(.GBL)" at 12195.81,7130.94 h34
  text "2.8mil" at 12759.33,7130.94 h34
  text "Bottom Solder Mask" at 11300,7034.19 h34
  text "(.GBS)" at 12195.81,7034.19 h34
  text "Solder Resist" at 13362.04,7034.19 h34
  text ".Layer_Name" at 517,-918.49 h60
M13 Component Bodies Top:
  text ".Layer_Name" at 517,-918.49 h60
M14 Component Bodies Bottom:
  text ".Layer_Name" at 517,-918.49 h60
M15 Courtyards Top:
  text ".Layer_Name" at 517,-918.49 h60
M16 Courtyards Bottom:
  text ".Layer_Name" at 517,-918.49 h60
Drill Drawing:
  text ".legend" at 6262.5,3835.5 h60
  text "Drill Table" at 6287.5,3650.5 h60
  text ".Layer_Name" at 517,-918.49 h60

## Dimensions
0,0 to 40,600 on M2 Board Dimensions
0,-2 to 1500,0 on M2 Board Dimensions
-60,-470.5 to 940,-470.5 on M2 Board Dimensions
